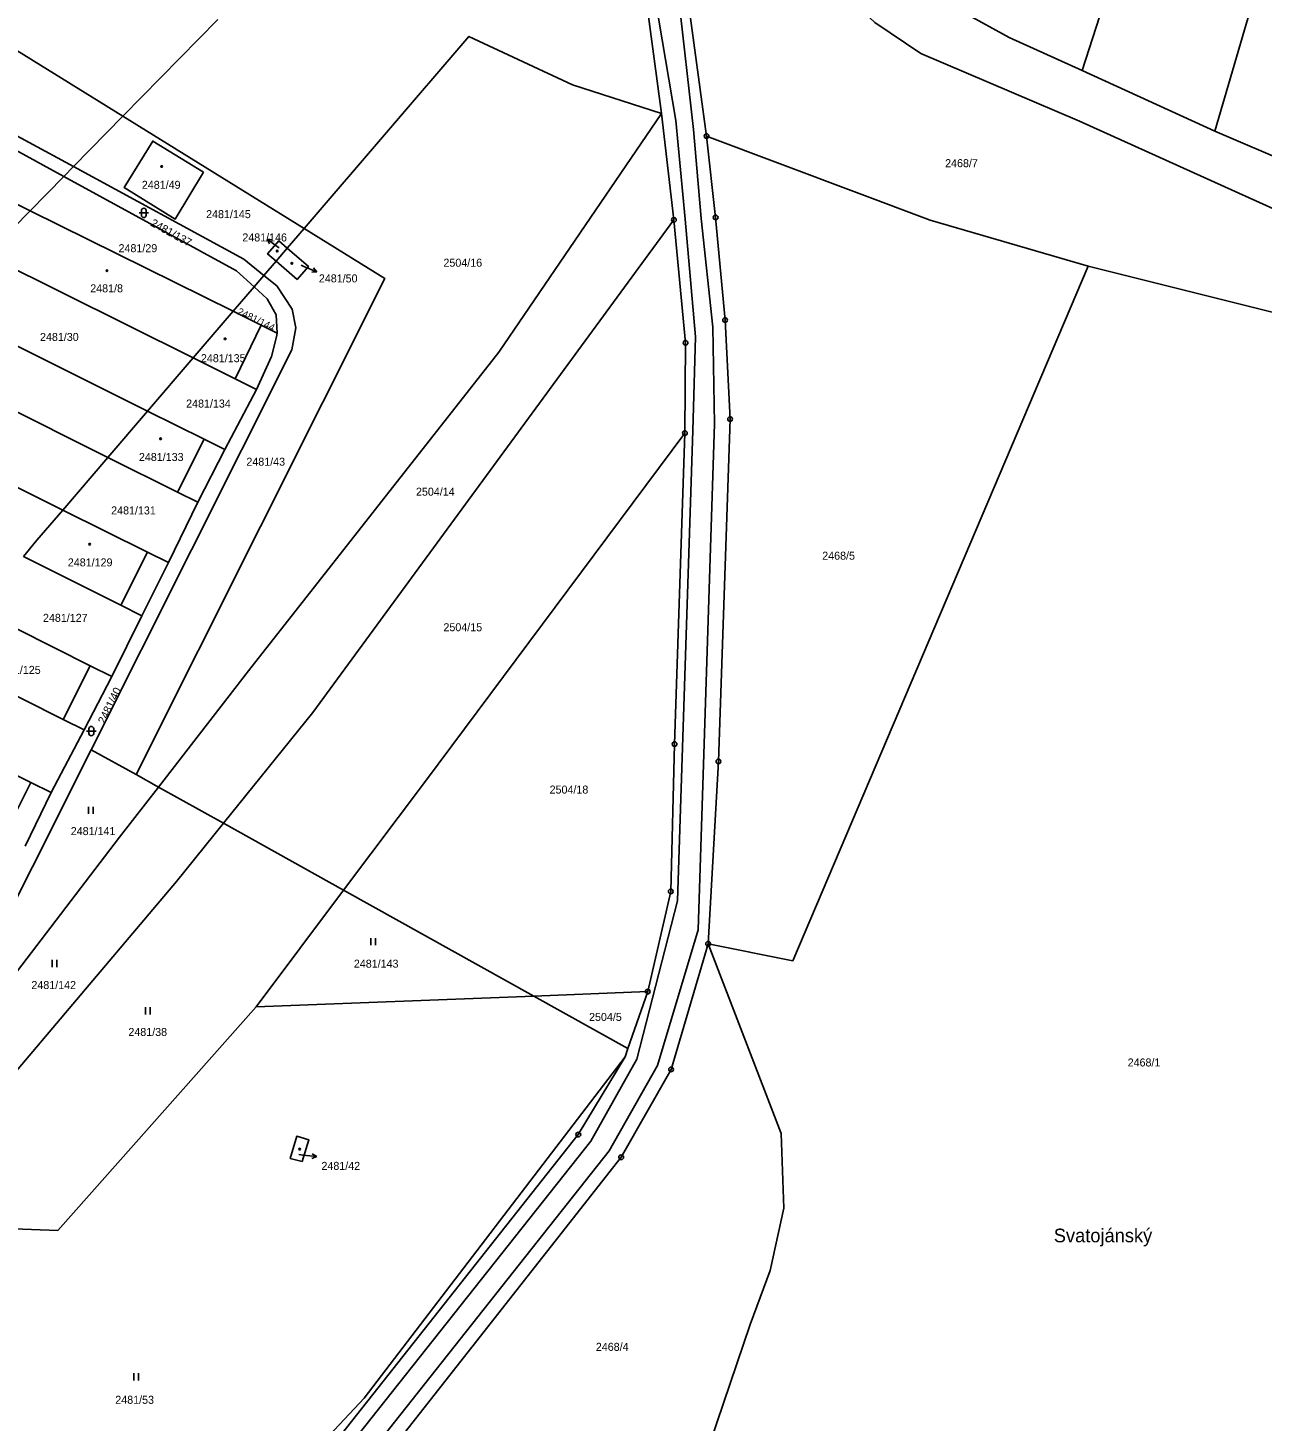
# Model space of a CAD drawing. Extents: x -733394 to -722299, y -1082822 to -1075049.
# Drawn here: x -729642.3 to -729380.2, y -1078691 to -1078394.9 of the extents above; entities that cross this region are included whole.
import ezdxf

# ---------------------------------------------------------------- set-up
doc = ezdxf.new("R2010")
doc.units = 0
for name, color, linetype in [('Hranice parcel', 7, 'Continuous'), ('Parcelní čísla', 7, 'Continuous'), ('Pop  PČ popisy', 7, 'Continuous'), ('Vnitřní kresba', 7, 'Continuous'), ('Značky bodu BP', 7, 'Continuous'), ('Značky budov', 7, 'Continuous'), ('Značky kultur', 7, 'Continuous')]:
    doc.layers.add(name, color=color, linetype=linetype)

msp = doc.modelspace()

# ---------------------------------------------------------------- linework, layer by layer
at = {"layer": 'Hranice parcel'}
for p, q in [((-729390.2, -1078416.88), (-729371.76, -1078353.68)), ((-729602, -1078393.13), (-729622.17, -1078413.7)), ((-729418.43, -1078403.98), (-729390.2, -1078416.88)), ((-729505.12, -1078435.73), (-729507.73, -1078413.09)), ((-729632.68, -1078424.42), (-729622.17, -1078413.7)), ((-729583.66, -1078437.55), (-729622.17, -1078413.7)), ((-729357.76, -1078430.87), (-729390.2, -1078416.88)), ((-729641.88, -1078433.81), (-729667.2, -1078421.29)), ((-729634.72, -1078426.5), (-729632.68, -1078424.42)), ((-729634.72, -1078426.5), (-729641.88, -1078433.81)), ((-729641.88, -1078433.81), (-729651.12, -1078443.23)), ((-729598.74, -1078455.14), (-729641.88, -1078433.81)), ((-729583.66, -1078437.55), (-729587.24, -1078441.73)), ((-729587.24, -1078441.73), (-729589.61, -1078444.5)), ((-729651.12, -1078443.23), (-729607.24, -1078465.06)), ((-729589.61, -1078444.5), (-729592.2, -1078447.51)), ((-729592.2, -1078447.51), (-729594.29, -1078449.96)), ((-729598.74, -1078455.14), (-729594.29, -1078449.96)), ((-729616.92, -1078476.35), (-729662, -1078453.84)), ((-729607.24, -1078465.06), (-729598.74, -1078455.14)), ((-729670.5, -1078463.67), (-729625.35, -1078486.19)), ((-729616.92, -1078476.35), (-729607.24, -1078465.06)), ((-729593.81, -1078471.75), (-729600.52, -1078484.53)), ((-729634.94, -1078497.37), (-729680.06, -1078474.91)), ((-729625.35, -1078486.19), (-729616.92, -1078476.35)), ((-729634.94, -1078497.37), (-729625.35, -1078486.19)), ((-729600.52, -1078484.53), (-729606.21, -1078495.73)), ((-729606.21, -1078495.73), (-729612.48, -1078508.55)), ((-729612.48, -1078508.55), (-729618.1, -1078519.82)), ((-729618.1, -1078519.82), (-729624.53, -1078532.73)), ((-729624.53, -1078532.73), (-729630.41, -1078544.09)), ((-729637.38, -1078557.4), (-729630.41, -1078544.09)), ((-729628.92, -1078548.33), (-729619.36, -1078553.58)), ((-729614.6, -1078556.23), (-729619.36, -1078553.58)), ((-729642.91, -1078568.82), (-729637.38, -1078557.4)), ((-729600.79, -1078563.93), (-729614.6, -1078556.23)), ((-729575.27, -1078578.15), (-729600.79, -1078563.93)), ((-729593.85, -1078602.95), (-729575.27, -1078578.15)), ((-729534.9, -1078600.64), (-729575.27, -1078578.15)), ((-729534.9, -1078600.64), (-729593.85, -1078602.95)), ((-729510.69, -1078599.69), (-729534.9, -1078600.64)), ((-729514.9, -1078611.78), (-729534.9, -1078600.64)), ((-729514.9, -1078611.78), (-729510.69, -1078599.69)), ((-729515.49, -1078613.53), (-729514.9, -1078611.78))]:
    msp.add_line(p, q, dxfattribs=at)
for points in [[(-729418.43, -1078403.98), (-729395.2, -1078332.02), (-729394.9, -1078331.26)], [(-729622.17, -1078413.7), (-729652.75, -1078394.76), (-729667.92, -1078376.99), (-729693.36, -1078374.72), (-729784.53, -1078338.02), (-729799.58, -1078367.74)], [(-729507.73, -1078413.09), (-729510.98, -1078388.79), (-729507.77, -1078343.87)], [(-729499.66, -1078351.2), (-729502.21, -1078388.15), (-729498.18, -1078417.94)], [(-729331.55, -1078454.28), (-729418.96, -1078414.78), (-729452.64, -1078400.36), (-729462.45, -1078393.8), (-729474.3, -1078382.57), (-729499.66, -1078351.2)], [(-729632.68, -1078424.42), (-729679.8, -1078398.89), (-729771.23, -1078357.56), (-729774.51, -1078357.52), (-729778.08, -1078358.98), (-729781.2, -1078363.35), (-729791.42, -1078382.99)], [(-729452.47, -1078386.72), (-729433.94, -1078396.95), (-729418.43, -1078403.98)], [(-729507.73, -1078413.09), (-729526.63, -1078407.05), (-729548.66, -1078396.73), (-729583.66, -1078437.55)], [(-729634.72, -1078426.5), (-729665.37, -1078409.75), (-729670.29, -1078409.53), (-729668.3, -1078413.28), (-729664.33, -1078415.51), (-729667.2, -1078421.29)], [(-729507.73, -1078413.09), (-729542.28, -1078463.83), (-729595.47, -1078531.53), (-729614.6, -1078556.23)], [(-729605.02, -1078425.62), (-729615.83, -1078418.97), (-729621.9, -1078428.84), (-729611.05, -1078435.55), (-729605.02, -1078425.62)], [(-729498.18, -1078417.94), (-729496.25, -1078435.22), (-729494.25, -1078457), (-729493.19, -1078478.04), (-729495.65, -1078550.8), (-729497.87, -1078589.54)], [(-729417.11, -1078445.59), (-729450.67, -1078435.82), (-729498.18, -1078417.94)], [(-729592.2, -1078447.51), (-729596.44, -1078444.05), (-729632.68, -1078424.42)], [(-729594.29, -1078449.96), (-729598.03, -1078446.56), (-729634.72, -1078426.5)], [(-729600.79, -1078563.93), (-729581.79, -1078540.36), (-729505.12, -1078435.73)], [(-729502.79, -1078481.02), (-729502.65, -1078461.84), (-729505.12, -1078435.73)], [(-729619.36, -1078553.58), (-729566.54, -1078448.15), (-729583.66, -1078437.55)], [(-729589.61, -1078444.5), (-729591.41, -1078442.95), (-729589.03, -1078440.19), (-729587.24, -1078441.73)], [(-729587.24, -1078441.73), (-729582.76, -1078445.61), (-729585.14, -1078448.36), (-729589.61, -1078444.5)], [(-729417.11, -1078445.59), (-729479.87, -1078593.14), (-729497.87, -1078589.54)], [(-729331.55, -1078454.28), (-729338.97, -1078465.08), (-729417.11, -1078445.59)], [(-729628.92, -1078548.33), (-729586.28, -1078463.37), (-729585.43, -1078458.63), (-729586.21, -1078454.69), (-729589.45, -1078449.76), (-729592.2, -1078447.51)], [(-729594.29, -1078449.96), (-729591.53, -1078452.47), (-729589.59, -1078455.89), (-729589.41, -1078459.77)], [(-729589.41, -1078459.77), (-729592.76, -1078458.1), (-729598.74, -1078455.14)], [(-729589.41, -1078459.77), (-729589.54, -1078460.61), (-729590.61, -1078464.78), (-729593.81, -1078471.75)], [(-729593.81, -1078471.75), (-729598.33, -1078469.5), (-729607.24, -1078465.06)], [(-729600.52, -1078484.53), (-729604.9, -1078482.35), (-729616.92, -1078476.35)], [(-729575.27, -1078578.15), (-729557.9, -1078554.96), (-729502.79, -1078481.02)], [(-729510.69, -1078599.69), (-729505.78, -1078578.41), (-729504.99, -1078547.11), (-729502.79, -1078481.02)], [(-729606.21, -1078495.73), (-729610.55, -1078493.57), (-729625.35, -1078486.19)], [(-729643.3, -1078507.28), (-729640.42, -1078503.76), (-729634.94, -1078497.37)], [(-729612.48, -1078508.55), (-729616.96, -1078506.32), (-729634.94, -1078497.37)], [(-729618.1, -1078519.82), (-729622.62, -1078517.57), (-729643.3, -1078507.28)], [(-729624.53, -1078532.73), (-729629.12, -1078530.45), (-729652.59, -1078518.64)], [(-729630.41, -1078544.09), (-729634.84, -1078541.88), (-729660.87, -1078528.77)], [(-729637.38, -1078557.4), (-729641.68, -1078555.26), (-729670.57, -1078540.66)], [(-729666.48, -1078623.93), (-729666.28, -1078622.77), (-729628.92, -1078548.33)], [(-729666.48, -1078623.93), (-729622.87, -1078566.91), (-729614.6, -1078556.23)], [(-729600.79, -1078563.93), (-729610.74, -1078576.27), (-729668.43, -1078644.41)], [(-729579.75, -1078715.63), (-729516.32, -1078634.88), (-729505.72, -1078616.24), (-729497.87, -1078589.54)], [(-729497.87, -1078589.54), (-729482.31, -1078629.84), (-729481.74, -1078645.69), (-729484.68, -1078658.92), (-729488.91, -1078670.41), (-729508.65, -1078728.69)], [(-729668.43, -1078644.41), (-729647.17, -1078650.03), (-729635.97, -1078650.42), (-729593.85, -1078602.95)], [(-729637.39, -1078759.99), (-729615.7, -1078741.31), (-729595.43, -1078718.66), (-729525.42, -1078630.07), (-729515.49, -1078613.53)], [(-729515.49, -1078613.53), (-729570.92, -1078686.09), (-729592.08, -1078708.69), (-729623.45, -1078742.19), (-729636.37, -1078756.57)], [(-729584.05, -1078635.78), (-729582.67, -1078631.18), (-729585.21, -1078630.42), (-729586.6, -1078635.15), (-729584.05, -1078635.78)]]:
    msp.add_lwpolyline(points, dxfattribs=at)
at = {"layer": 'Pop  PČ popisy'}
for p, q in [((-729589.08, -1078441.57), (-729591.51, -1078439.81)), ((-729591.51, -1078439.81), (-729590.4, -1078439.99)), ((-729591.51, -1078439.81), (-729590.99, -1078440.8)), ((-729588.99, -1078441.63), (-729589.08, -1078441.57)), ((-729584.3, -1078445.38), (-729583.71, -1078445.62)), ((-729583.71, -1078445.62), (-729580.93, -1078446.74)), ((-729580.93, -1078446.74), (-729582.04, -1078446.83)), ((-729580.93, -1078446.74), (-729581.67, -1078445.91)), ((-729584.75, -1078634.33), (-729583.96, -1078634.42)), ((-729583.96, -1078634.42), (-729580.98, -1078634.73)), ((-729580.98, -1078634.73), (-729582.02, -1078635.13)), ((-729580.98, -1078634.73), (-729581.92, -1078634.13))]:
    msp.add_line(p, q, dxfattribs=at)
at = {"layer": 'Vnitřní kresba'}
for p, q in [((-729509.11, -1078388.65), (-729504.69, -1078414.63)), ((-729500.94, -1078416.54), (-729504.16, -1078388.29)), ((-729504.69, -1078414.63), (-729502.74, -1078435.59)), ((-729499.34, -1078435.4), (-729500.94, -1078416.54)), ((-729502.74, -1078435.59), (-729500.52, -1078460.61)), ((-729496.86, -1078458.5), (-729499.34, -1078435.4)), ((-729598.33, -1078469.5), (-729592.76, -1078458.1)), ((-729496.53, -1078479.08), (-729496.86, -1078458.5)), ((-729500.52, -1078460.61), (-729501.12, -1078480.5)), ((-729504.36, -1078580.41), (-729501.12, -1078480.5)), ((-729496.53, -1078479.08), (-729499.96, -1078586.6)), ((-729610.55, -1078493.57), (-729604.9, -1078482.35)), ((-729622.62, -1078517.57), (-729616.96, -1078506.32)), ((-729634.84, -1078541.88), (-729629.12, -1078530.45)), ((-729647.38, -1078566.59), (-729641.68, -1078555.26)), ((-729512.96, -1078614.06), (-729504.36, -1078580.41)), ((-729499.96, -1078586.6), (-729508.6, -1078615.37)), ((-729522.76, -1078631.47), (-729512.96, -1078614.06)), ((-729508.6, -1078615.37), (-729518.88, -1078633.53)), ((-729593.26, -1078720.48), (-729522.76, -1078631.47)), ((-729518.88, -1078633.53), (-729589.87, -1078723.31))]:
    msp.add_line(p, q, dxfattribs=at)
at = {"layer": 'Značky bodu BP'}
for centre, radius in [((-729498.18, -1078417.94), 0.5), ((-729498.18, -1078417.94), 0.0303), ((-729505.12, -1078435.73), 0.5), ((-729505.12, -1078435.73), 0.0303), ((-729496.25, -1078435.22), 0.5), ((-729496.25, -1078435.22), 0.0303), ((-729494.25, -1078457), 0.5), ((-729494.25, -1078457), 0.0303), ((-729502.65, -1078461.84), 0.5), ((-729502.65, -1078461.84), 0.0303), ((-729493.19, -1078478.04), 0.5), ((-729493.19, -1078478.04), 0.0303), ((-729502.79, -1078481.02), 0.5), ((-729502.79, -1078481.02), 0.0303), ((-729504.99, -1078547.11), 0.5), ((-729504.99, -1078547.11), 0.0303), ((-729495.65, -1078550.8), 0.5), ((-729495.65, -1078550.8), 0.0303), ((-729505.78, -1078578.41), 0.5), ((-729505.78, -1078578.41), 0.0303), ((-729497.87, -1078589.54), 0.5), ((-729497.87, -1078589.54), 0.0303), ((-729510.69, -1078599.69), 0.5), ((-729510.69, -1078599.69), 0.0303), ((-729505.72, -1078616.24), 0.5), ((-729505.72, -1078616.24), 0.0303), ((-729525.42, -1078630.07), 0.5), ((-729525.42, -1078630.07), 0.0303), ((-729516.32, -1078634.88), 0.5), ((-729516.32, -1078634.88), 0.0303)]:
    msp.add_circle(centre, radius, dxfattribs=at)
at = {"layer": 'Značky budov'}
for centre in [(-729613.93, -1078424.37), (-729589.37, -1078442.33), (-729586.26, -1078444.97), (-729625.52, -1078446.52), (-729600.44, -1078461), (-729614.16, -1078482.24), (-729629.2, -1078504.63), (-729584.6, -1078633.16)]:
    msp.add_circle(centre, 0.175, dxfattribs=at)
at = {"layer": 'Značky kultur'}
for p, q in [((-729618.21, -1078433.74), (-729618.21, -1078434.74)), ((-729617.21, -1078434.74), (-729617.21, -1078433.74)), ((-729618.71, -1078434.24), (-729616.71, -1078434.24)), ((-729629.86, -1078544.35), (-729627.86, -1078544.35)), ((-729629.36, -1078543.85), (-729629.36, -1078544.85)), ((-729628.36, -1078544.85), (-729628.36, -1078543.85)), ((-729629.49, -1078561.94), (-729629.49, -1078560.44)), ((-729628.49, -1078561.94), (-729628.49, -1078560.44)), ((-729569.48, -1078589.86), (-729569.48, -1078588.36)), ((-729568.48, -1078589.86), (-729568.48, -1078588.36)), ((-729637.17, -1078594.47), (-729637.17, -1078592.97)), ((-729636.17, -1078594.47), (-729636.17, -1078592.97)), ((-729617.38, -1078604.53), (-729617.38, -1078603.03)), ((-729616.38, -1078604.53), (-729616.38, -1078603.03)), ((-729619.84, -1078682.29), (-729619.84, -1078680.79)), ((-729618.84, -1078682.29), (-729618.84, -1078680.79))]:
    msp.add_line(p, q, dxfattribs=at)
for centre, start, end in [((-729617.71, -1078433.74), 0, 180), ((-729617.71, -1078434.74), 180, 359.9879), ((-729628.86, -1078543.85), 0, 180), ((-729628.86, -1078544.85), 180, 359.9879)]:
    msp.add_arc(centre, 0.5, start, end, dxfattribs=at)

# ---------------------------------------------------------------- texts
at = {"layer": 'Parcelní čísla'}
for s, p in [('2468/7', (-729447.51, -1078424.53)), ('2481/49', (-729618.13, -1078429.13)), ('2481/145', (-729604.48, -1078435.36)), ('2481/146', (-729596.79, -1078440.31)), ('2481/29', (-729623.08, -1078442.59)), ('2504/16', (-729554.07, -1078445.68)), ('2481/50', (-729580.53, -1078449.01)), ('2481/8', (-729629.09, -1078451.12)), ('2481/30', (-729639.76, -1078461.45)), ('2481/135', (-729605.58, -1078465.96)), ('2481/134', (-729608.72, -1078475.6)), ('2481/133', (-729618.75, -1078486.96)), ('2481/43', (-729595.93, -1078487.96)), ('2504/14', (-729559.9, -1078494.33)), ('2481/131', (-729624.65, -1078498.31)), ('2481/129', (-729633.85, -1078509.35)), ('2468/5', (-729473.61, -1078507.93)), ('2481/127', (-729639.13, -1078521.13)), ('2504/15', (-729554.07, -1078523.13)), ('2481/125', (-729649.1, -1078532.19)), ('2504/18', (-729531.52, -1078557.62)), ('2481/141', (-729633.23, -1078566.44)), ('2481/143', (-729573.1, -1078594.61)), ('2481/142', (-729641.59, -1078599.15)), ('2504/5', (-729523.14, -1078605.93)), ('2481/38', (-729620.99, -1078609.12)), ('2468/1', (-729408.74, -1078615.6)), ('2481/42', (-729579.98, -1078637.57)), ('2468/4', (-729521.7, -1078676.02)), ('2481/53', (-729623.77, -1078687.27))]:
    msp.add_text(s, height=1.7, dxfattribs=at).set_placement(p)
for s, height, rotation, p in [('2481/137', 1.7, 331, (-729616.44, -1078436.88)), ('2481/144', 1.53, 334, (-729598.01, -1078455.7)), ('2481/40', 1.7, 64, (-729626.03, -1078542.98))]:
    msp.add_text(s, height=height, rotation=rotation, dxfattribs=at).set_placement(p)
at = {"layer": 'Pop  PČ popisy'}
msp.add_text('Svatojánský', height=2.9, dxfattribs=at).set_placement((-729424.43, -1078652.96))

doc.saveas('drawing.dxf')
